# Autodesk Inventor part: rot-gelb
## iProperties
Created: 2004-10
Part Number: rot-gelb
Document SubType Name: Modeling
Designer: sahrens
Manufacturer: Standard
Standards Organization: Custom
Author: sahrens
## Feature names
1. Extrusion1
2. Rundung2 [Fillet]
